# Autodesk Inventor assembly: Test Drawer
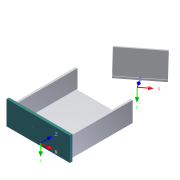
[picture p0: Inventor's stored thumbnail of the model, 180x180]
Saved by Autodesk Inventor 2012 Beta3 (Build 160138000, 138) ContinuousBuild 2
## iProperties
Created: 2011-02
Part Number: Test Drawer
Document SubType Name: Assembly
Designer: Beta-8540w
Author: Beta-8540w
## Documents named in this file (8)
- C:\Inventor 2012 Essentials\Assemblies\Chapter 15\c15-01.iam
- C:\Inventor 2012 Essentials\Parts\Chapter 15\c15-04.ipt
- C:\Inventor 2012 Essentials\Parts\Chapter 15\c15-03.ipt
- C:\Inventor 2012 Essentials\Parts\Chapter 15\c15-09.ipt
- C:\Inventor 2012 Essentials\Parts\Chapter 15\c15-10.ipt
- C:\Inventor 2012 Essentials\Parts\Chapter 15\c15-06.ipt
- C:\Inventor 2012 Essentials\Parts\Chapter 15\c15-07.ipt
- C:\Inventor 2012 Essentials\Parts\Chapter 15\c15-08.ipt
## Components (9 placed, 7 different names)
1. c15-04:1 — Flush:3, Flush:6, Flush:9, Flush:12, Flush:24
2. c15-09:1 — Flush:3
3. c15-09:2 — Flush:6
4. c15-10:1 — Flush:9
5. c15-10:2 — Flush:12
6. c15-06:1
7. c15-07:1
8. c15-08:1 — Flush:24
9. c15-03:1
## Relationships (5: Flush 5)
- Flush:3: c15-04:1 ↔ c15-09:1
- Flush:6: c15-04:1 ↔ c15-09:2
- Flush:9: c15-04:1 ↔ c15-10:1
- Flush:12: c15-04:1 ↔ c15-10:2
- Flush:24: c15-04:1 ↔ c15-08:1
